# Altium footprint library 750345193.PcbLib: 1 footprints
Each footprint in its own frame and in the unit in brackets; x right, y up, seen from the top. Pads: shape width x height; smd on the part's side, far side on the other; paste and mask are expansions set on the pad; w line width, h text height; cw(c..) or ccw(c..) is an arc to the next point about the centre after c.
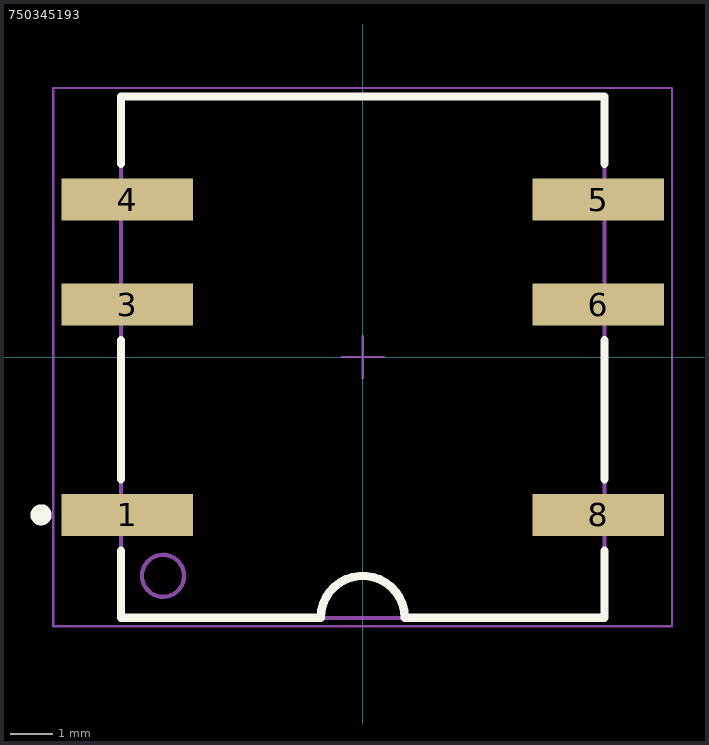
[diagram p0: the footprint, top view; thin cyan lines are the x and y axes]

## 750345193 [mm]
pads (6):
  rect 3.12x1 smd: 1(-5.6,-3.75) 3(-5.6,1.25) 4(-5.6,3.75) 5(5.6,3.75) 6(5.6,1.25) 8(5.6,-3.75)
Top Overlay:
  circle w0.25: c-7.65,-3.75 r0.125
  lines w0.2: -5.75,-4.6 -5.75,-6.2 -1,-6.2 cw(c0,-6.2) 1,-6.2 5.75,-6.2 5.75,-4.6 ; -5.75,-2.9 -5.75,0.4 ; -5.75,4.6 -5.75,6.2 5.75,6.2 5.75,4.6 ; 5.75,-2.9 5.75,0.4
Top Assembly:
  circle w0.1: c-4.75,-5.2 r0.5
  lines w0.1: -5.75,-6.2 5.75,-6.2 5.75,6.2 -5.75,6.2 -5.75,-6.2
  text ".Designator" at -7.498,-0.5 h1.5
Top 3D Body:
  circle w0.1: c-4.75,-5.2 r0.5
  lines w0.1: -5.75,-6.2 -1,-6.2 cw(c0,-6.2) 1,-6.2 5.75,-6.2 5.75,6.2 -5.75,6.2 -5.75,-6.2
Top Courtyard:
  lines w0.05: -0.5,0 0.5,0 ; 0,-0.5 0,0.5 ; -7.36,-6.4 -7.36,6.4 7.36,6.4 7.36,-6.4 -7.36,-6.4
3D body "EP10_7052_MP2-7.STEP": height 12.51, standoff 0, extent -6.598,-6.065 6.597,6.065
